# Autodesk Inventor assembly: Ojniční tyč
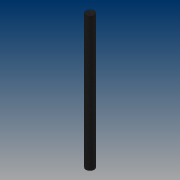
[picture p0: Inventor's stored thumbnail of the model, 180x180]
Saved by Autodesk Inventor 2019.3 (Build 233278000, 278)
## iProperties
Created: 2019-01
Part Number: Ojniční tyč
Material: Všeobecné
Document SubType Name: Assembly
Designer: B-hon
Author: B-hon
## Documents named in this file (3)
- C:\Users\B-hon\OneDrive\Plocha\Bakalářka22\Ojnice\Ojniční tyč.iam
- C:\Users\B-hon\OneDrive\Plocha\Bakalářka22\Ojnice\18x1,5.ipt
- C:\Users\B-hon\OneDrive\Plocha\Bakalářka22\Ojnice\Matice.ipt
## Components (3 placed, 2 different names)
1. 18x1,5:1 — Vložit:1, Vložit:2
2. Matice:1 — Vložit:1
3. Matice:2 — Vložit:2
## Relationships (2: Insert 2)
- Vložit:1 [Insert]: 18x1,5:1 ↔ Matice:1
- Vložit:2 [Insert]: 18x1,5:1 ↔ Matice:2
